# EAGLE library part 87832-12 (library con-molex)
Milli-Grid Header 2.00mm (.079") Pitch
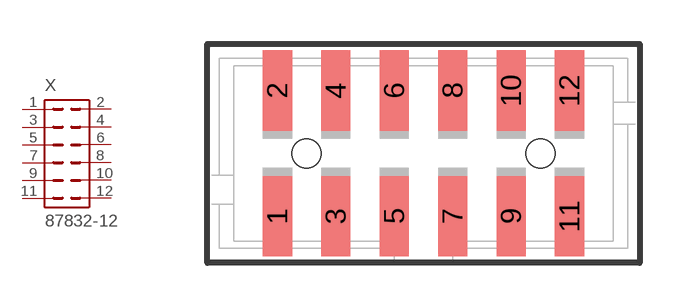
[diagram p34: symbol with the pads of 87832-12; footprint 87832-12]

Designator prefix X

## 87832-12 (OC_FARNELL: 1756948; OC_NEWARK: unknown)  [87832-12]
1  1  pas
2  2  pas
3  3  pas
4  4  pas
5  5  pas
6  6  pas
7  7  pas
8  8  pas
9  9  pas
10  10  pas
11  11  pas
12  12  pas

## Footprint 87832-12 (pad centres in mm)
PCB Headers 2.00mm (.079") Pitch Milli-Grid Header, Vertical, Shrouded
smd 1 x 2.75: 1 -5,-2.15; 2 -5,2.15; 3 -3,-2.15; 4 -3,2.15; 5 -1,-2.15; 6 -1,2.15; 7 1,-2.15; 8 1,2.15; 9 3,-2.15; 10 3,2.15; 11 5,-2.15; 12 5,2.15
hole 1 at -4,0
hole 1 at 4,0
